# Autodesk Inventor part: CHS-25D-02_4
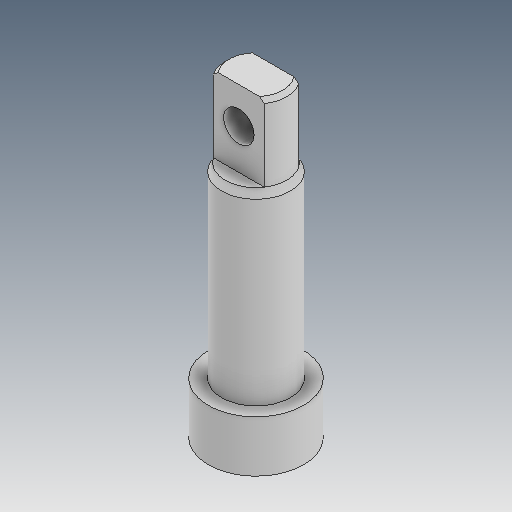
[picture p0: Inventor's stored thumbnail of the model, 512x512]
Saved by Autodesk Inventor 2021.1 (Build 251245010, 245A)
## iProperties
Created: 2019-04
Part Number: CHS-25D-02_4
Material: Ogólny
Document SubType Name: Modeling
Designer: user
Density: 1 g/cm^3
Appearance: Domyślna
Author: user
Revision Number: ÈÎºÎ
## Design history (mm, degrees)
feature "ÊäÈë1"
feature "ÊäÈë2"
node "Bryła1"
node "Bryła2"
